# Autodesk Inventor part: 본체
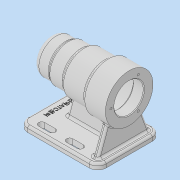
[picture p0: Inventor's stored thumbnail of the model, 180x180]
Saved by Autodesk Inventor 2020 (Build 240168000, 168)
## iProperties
Created: 2021-10
Part Number: 본체
Material: 일반
Document SubType Name: Modeling
Designer: user
Density: 1 g/cm^3
Appearance: 기본값
Author: user
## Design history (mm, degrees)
sketch "스케치1"
  geometry: L1 (-45, 56)-(45, 56); L2 (45, 56)-(45, -56); L3 (45, -56)-(-45, -56); L4 (-45, -56)-(-45, 56); L5 (-45, 56)-(45, -56); L6 (45, 56)-(-45, -56); 1 further point
  constraints: 12 end point, 2 midpoint, 2 parallel, 1 horizontal, 1 perpendicular
  dimensions: "d0" = 112 distance of L1.end L2.end; "d1" = 90 distance of L2.end L3.end
extrude "돌출1" new body sketch "스케치1" distance "d2" = 8; taper "d3" = 0 deg
fillet "모깎기1" dims "d4" = 12
fillet "모깎기2" dims "d5" = 3
sketch "스케치2"
  geometry: L1 (70, -56)-(70, 56); L2 (70, -56)-(95, -56); L3 (95, -56)-(95, -32); L4 (95, -32)-(97, -32); L5 (97, -32)-(97, -10); L6 (97, -10)-(100, -10); L7 (100, -10)-(100, 24); L8 (100, 24)-(104, 24); L9 (104, 24)-(104, 56); L10 (104, 56)-(70, 56); L11 (5, -56)-(0, -56) reference; L12 (0, -44)-(0, 44) reference; 3 further points
  constraints: 20 end point, 7 perpendicular, 2 midpoint, 2 vertical, 1 horizontal, 1 horizontal alignment
  dimensions: "d7" = 24 distance between parallel lines of L4 L2; "d8" = 112 distance between parallel lines of L10 L2; "d9" = 46 distance between parallel lines of L6 L2; "d10" = 80 distance between parallel lines of L2 L8; "d12" = 54 diameter of L5 L1; "d13" = 60 diameter of L7 L1; "d14" = 68 diameter of L9 L1; "d15" = 50 diameter of L3 L1; "d16" = 70 distance between parallel lines of L12 L1
revolve "회전1" sketch "스케치2" stored, may be unused: angle "d17" = 90 deg
sketch "스케치3"
  geometry: C1 r 34 at (0, 0) reference; 2 further points
  constraints: 1 coincident
hole "구멍1" sketch "스케치3" at (0, 0) diameter "d18" = 42; stored, may be unused: countersink angle "d22" = 90 deg, drill point angle "d24" = 0 deg; dims "d19" = 6, "d20" = 42, "d21" = 15, "d23" = 15
sketch "스케치4"
  geometry: C1 r 21 at (0, 0) reference; 2 further points
  constraints: 1 coincident
hole "구멍2" sketch "스케치4" at (0, 0) diameter "d25" = 48; stored, may be unused: countersink angle "d29" = 90 deg, drill point angle "d31" = 0 deg; dims "d26" = 6, "d27" = 48, "d28" = 54, "d30" = 54
sketch "스케치5"
  geometry: C1 r 24 at (0, 0) reference; 2 further points
  constraints: 1 coincident
hole "구멍3" sketch "스케치5" at (0, 0) diameter "d32" = 42; stored, may be unused: countersink angle "d36" = 90 deg, drill point angle "d38" = 0 deg; dims "d33" = 6, "d34" = 48, "d35" = 54, "d37" = 12
sketch "스케치6"
  geometry: C1 r 21 at (0, 0) reference; 2 further points
  constraints: 1 coincident
hole "구멍4" sketch "스케치6" at (0, 0) diameter "d39" = 35; stored, may be unused: countersink angle "d43" = 90 deg, drill point angle "d45" = 0 deg; dims "d40" = 6, "d41" = 48, "d42" = 54, "d44" = 18
sketch "스케치7"
  geometry: C1 r 17.5 at (0, 0) reference; 2 further points
  constraints: 1 coincident
hole "구멍5" sketch "스케치7" at (0, 0) diameter "d46" = 32; stored, may be unused: countersink angle "d50" = 90 deg, drill point angle "d52" = 0 deg; dims "d47" = 6, "d48" = 48, "d49" = 54, "d51" = 4
sketch "스케치8"
  geometry: C1 r 16 at (0, 0) reference; 2 further points
  constraints: 1 coincident
hole "구멍6" sketch "스케치8" at (0, 0) diameter "d53" = 21; stored, may be unused: countersink angle "d57" = 90 deg, drill point angle "d59" = 0 deg; dims "d54" = 6, "d55" = 48, "d56" = 54, "d58" = 3
fillet "모깎기3" dims "d60" = 3
fillet "모깎기4" dims "d61" = 0.3
chamfer "모따기1" distance "d62" = 1; stored, may be unused: second distance "d63" = 2, angle "d64" = 45 deg
fillet "모깎기5" dims "d65" = 3
fillet "모깎기6" dims "d66" = 8
sketch "스케치9"
  geometry: L1 (-33, 36)-(-33, 21); L2 (-37.5, 36)-(-37.5, 21); L3 (-28.5, 21)-(-28.5, 36); L4 (33, 56)-(-33, 56) reference; L5 (-33, -4)-(-33, -19); L6 (-37.5, -4)-(-37.5, -19); L7 (-28.5, -19)-(-28.5, -4); L8 (33, 56)-(-33, 56) reference; L9 (0, 56)-(0, -56); L10 (-33, -56)-(33, -56) reference; L11 (37.5, -4)-(37.5, -19); L12 (33, -4)-(33, -19); L13 (28.5, -19)-(28.5, -4); L14 (28.5, 21)-(28.5, 36); L15 (33, 36)-(33, 21); L16 (37.5, 36)-(37.5, 21); A1 r 4.5 centre (-33, 36) between (-28.5, 36) and (-37.5, 36); A2 r 4.5 centre (-33, 21) between (-37.5, 21) and (-28.5, 21); A3 r 4.5 centre (-33, -4) between (-28.5, -4) and (-37.5, -4); A4 r 4.5 centre (-33, -19) between (-37.5, -19) and (-28.5, -19); A5 r 4.5 centre (33, -4) between (37.5, -4) and (28.5, -4); A6 r 4.5 centre (33, -19) between (28.5, -19) and (37.5, -19); A7 r 4.5 centre (33, 21) between (28.5, 21) and (37.5, 21); A8 r 4.5 centre (33, 36) between (37.5, 36) and (28.5, 36); 5 further points
  constraints: 34 end point, 16 point on circle, 14 symmetric about line, 8 centre point, 8 tangent, 4 midpoint, 2 parallel, 2 vertical, 4 other
  dimensions: "d68" = 15 distance of L1.start L1.end; "d69" = 9 distance between parallel lines of L2 L3; "d70" = 20 distance from line of L4 L1.start; "d71" = 33 horizontal distance of point (0, 0) point (-33, 28.5); "d72" = 9 distance between parallel lines of L6 L7; "d73" = 15 distance of L5.start L5.end; "d74" = 25 distance of L5.start L1.end; "d75" = 33 horizontal distance of point (-33, -11.5) point (0, 0)
extrude "돌출2" cut sketch "스케치9" extent not by distance; stored distance "d76" = 0; taper "d77" = 0 deg
sketch "스케치10"
  geometry: L1 (-4, -48)-(4, -48); L2 (4, -48)-(4, 29); L3 (4, 29)-(-4, 29); L4 (-4, 29)-(-4, -48); L5 (-33, -56)-(33, -56) reference; 1 further point
  constraints: 8 end point, 2 parallel, 1 horizontal, 1 perpendicular
  dimensions: "d78" = 8 distance between parallel lines of L5 L1; "d79" = 8 distance of L2.end L3.end; "d80" = 77 distance of L1.end L2.end; "d81" = 4 distance from line of L2 point (0, 0)
extrude "돌출3" join sketch "스케치10" stored distance "d82" = 8; taper "d83" = 0 deg
sketch "스케치11"
  geometry: L1 (-38, 0)-(-29, 0) reference; L2 (-33.5, 0)-(-24.5, 0) reference; L3 (-29, 0)-(37, 0) reference; L4 (32.5, 0)-(41.5, 0) reference; L5 (37, 0)-(46, 0) reference; L6 (-33.5, 0)-(-24.5, 0) reference; L7 (-41, -3)-(-41, -8) reference; L8 (27.409, 37.342)-(41, 0); L9 (49, -8)-(49, -3) reference; L10 (-19.409, 37.342)-(-33, 0); A1 r 34 centre (4, 62) between (8, 28.236) and (0, 28.236) reference; A2 r 34 centre (4, 62) between (0, 28.236) and (8, 28.236) reference; A3 r 34 centre (4, 62) between (-19.409, 37.342) and (27.409, 37.342); 1 further point
  constraints: 4 end point, 4 point on circle, 2 point on line, 1 centre point, 1 coincident
  dimensions: "d92" = 110 deg angle of L10 L1; "d93" = 8 distance from line of L7 L10.end; "d94" = 110 deg angle of L8 L5; "d95" = 8 distance from line of L9 L8.end
extrude "돌출4" join sketch "스케치11" distance "d96" = 8; taper "d97" = 0 deg
feature "면 기울기1" dims angle "d98" = 15 deg
fillet "모깎기7" dims "d99" = 3
fillet "모깎기8" dims "d100" = 3
sketch "스케치12"
  geometry: C1 r 10.5 at (0, 0) reference; C2 r 26 at (0, 0); 3 further points
  constraints: 2 horizontal alignment, 1 centre point, 1 coincident, 1 other
  dimensions: "d101" = 52 diameter of C2
hole "구멍7" sketch "스케치12" at (-26, 0) diameter "d102" = 3.242; stored, may be unused: countersink angle "d106" = 82 deg, drill point angle "d108" = 118 deg; dims "d103" = 8, "d104" = 3.023, "d105" = 54, "d107" = 11
sketch "스케치13"
  geometry: L1 (33, 56)-(-33, 56) reference; 2 further points
  constraints: 1 vertical alignment, 1 other
  dimensions: "d112" = 12 distance from line of L1 point (0, 44)
feature "엠보싱1" sketch "스케치13" dims "d0" = 112, "d1" = 90, "d7" = 24, "d8" = 112, "d9" = 46, "d10" = 80, "d12" = 54, "d13" = 60, "d14" = 68, "d15" = 50, "d16" = 70, "d113" = 0.5, "d114" = 0
node "솔리드1"
pattern_circular "원형 패턴1" dims angle "d110" = 360 deg
feature "A9D066F2-1C7D-4E18-AEED-F7BC21143FA4" dims "d18" = 42, "d19" = 6, "d20" = 42, "d21" = 15, "d22" = 90 deg, "d23" = 15, "d24" = 0
